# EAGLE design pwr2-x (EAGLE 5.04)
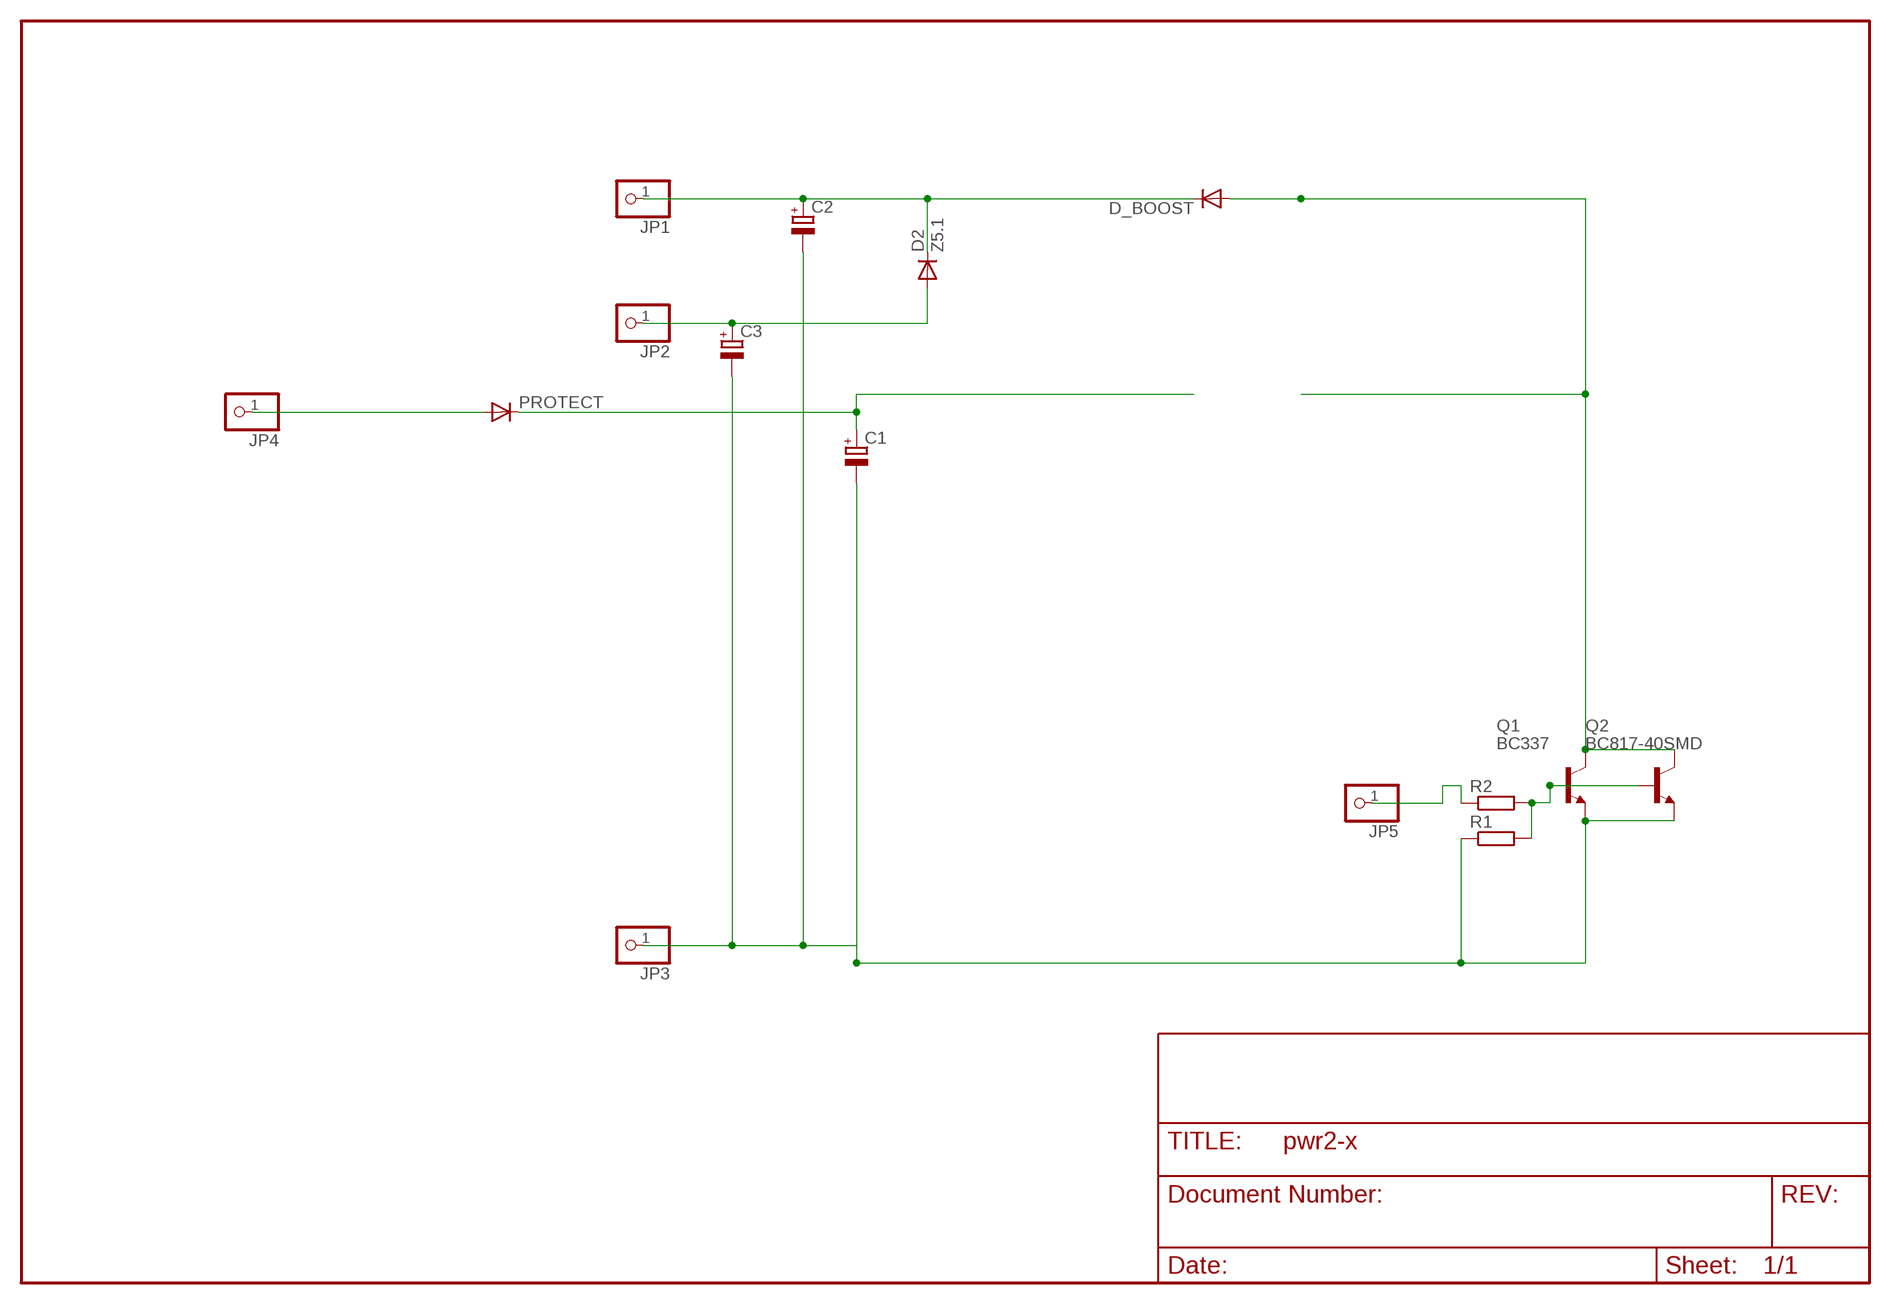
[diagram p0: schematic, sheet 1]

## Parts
C1  CPOL-EUE2.5-7  [E2,5-7]
C2  CPOL-EUE2.5-7  [E2,5-7]
C3  CPOL-EUE2-4  [E2-4]
D2  Z5.1  DIODE-D-7.5  [D-7.5]
D_BOOST  DIODE-D-10  [D-10]
JP1  PINHD-1X1  [1X01]
JP2  PINHD-1X1  [1X01]
JP3  PINHD-1X1  [1X01]
JP4  PINHD-1X1  [1X01]
JP5  PINHD-1X1  [1X01]
PROTECT  DIODE-D-5  [D-5]
Q1  BC337  [TO92]
Q2  BC817-40SMD  [SOT23-BEC]
R1  R-EU_0204/2V  [0204V]
R2  R-EU_0204/2V  [0204V]

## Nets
GND: C1.- C2.- C3.- JP3.1 Q1.1(E) Q2.E R1.1
HOTSPOT: D_BOOST.A Q1.3(C) Q2.C
N$1: Q1.2(B) Q2.B R1.2 R2.2
N$2: C1.+ PROTECT.C
N$3: JP5.1 R2.1
N$4: C3.+ D2.A JP2.1
N$6: JP4.1 PROTECT.A
N$7: C2.+ D2.C D_BOOST.C JP1.1

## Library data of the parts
C1-C3 = rcl(2):CPOL-EU: POLARIZED CAPACITOR, European symbol
D2 D_BOOST PROTECT = diode:DIODE-: DIODE
JP1-JP5 = pinhead:PINHD-1X1: PIN HEADER
Q1 = transistor-npn:BC337*: NPN Transistor
Q2 = transistor-npn:BC817*: NPN Transistor
R1 R2 = rcl-2:R-EU_: RESISTOR, European symbol

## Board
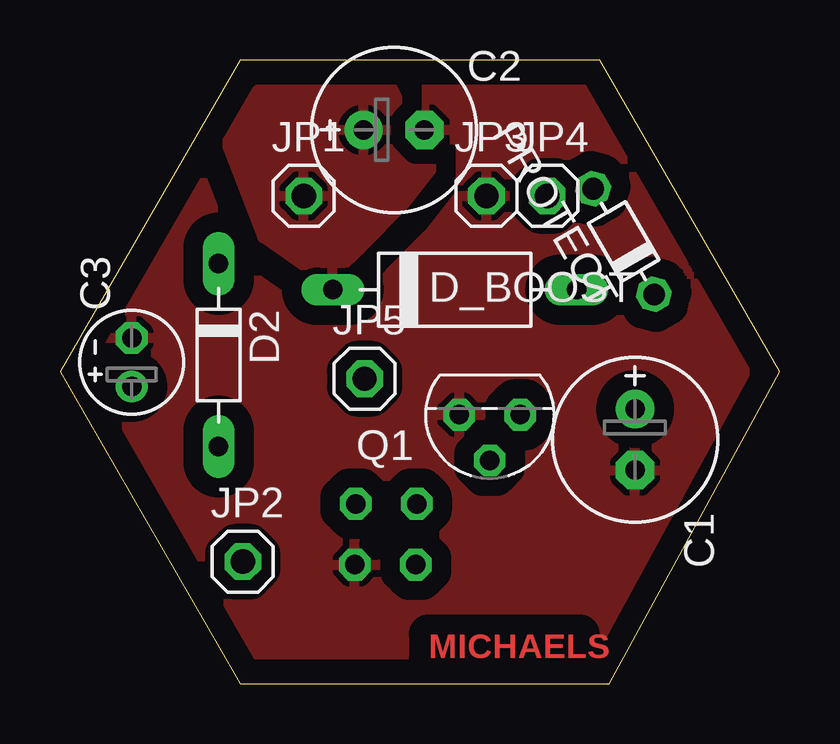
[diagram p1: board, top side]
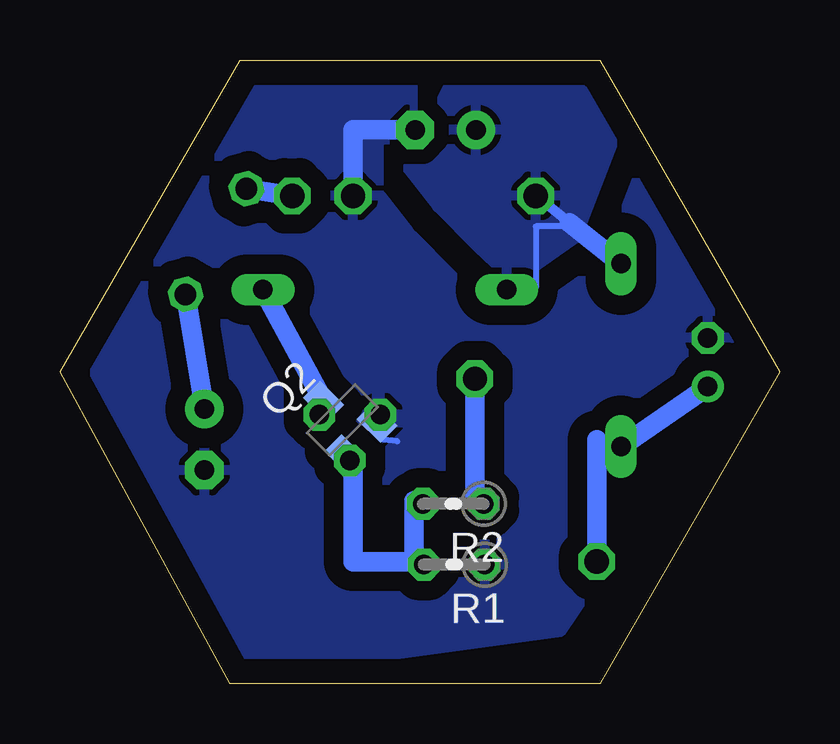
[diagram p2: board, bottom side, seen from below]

Size 30 x 25.98 mm. Coordinates in mm from the lower left corner, seen from the top.
Outline: 7.5,0 22.9,0 30,12.99 22.5,25.98 7.5,25.98 0,12.99 7.5,0
Copper layers (1*16): Top 0.035mm / dielectric 1.5mm / Bottom 0.035mm
Design rules "default": minimum track width 10mil, minimum drill 24mil, track to track 8mil, track to pad 8mil, pad to pad 8mil, via to via 8mil, smd to smd 8mil, copper to edge 40mil, drill to drill 8mil, minimum pad ring 10mil, minimum via ring 8mil, stop-mask expansion 4mil, vias tented up to drill 0mil, thermal gap 10mil

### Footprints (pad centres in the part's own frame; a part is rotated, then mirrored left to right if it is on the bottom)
E2,5-7 = drill 0.813 pad 1.6 round: + -1.27,0 | drill 0.813 pad 1.6 octagon: - 1.27,0
E2-4 = drill 0.813 pad 1.27 round: + -1.016,0 | drill 0.813 pad 1.27 octagon: - 1.016,0
D-7.5 = drill 0.813 long: A 3.81,0; C -3.81,0
D-10 = drill 0.813 long: A 5.08,0; C -5.08,0
1X01 = drill 1.016 octagon: 1 0,0
D-5 = drill 0.9 octagon: A 2.54,0; C -2.54,0
TO92 = drill 0.813 octagon: 1 1.27,0; 2 0,1.905; 3 -1.27,0
SOT23-BEC = smd 1 x 1.4: B -0.95,-1.1; C 0,1.1; E 0.95,-1.1
0204V = drill 0.813 octagon: 1 -1.27,0; 2 1.27,0

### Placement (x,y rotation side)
C1  23.98,10.16 270 top
C2  13.93,23.07 0 top
C3  2.99,13.39 90 top
D2  6.61,13.68 270 top
D_BOOST  16.45,16.41 0 top
JP1  10.16,20.32 0 top
JP2  7.62,5.08 0 top
JP3  17.78,20.32 0 top
JP4  20.32,20.32 0 top
JP5  12.7,12.7 0 top
PROTECT  23.5,18.41 120 top
Q1  17.92,11.2 180 top
Q2  18.23,10.98 45 bottom
R1  13.56,4.95 180 bottom
R2  13.6,7.49 180 bottom

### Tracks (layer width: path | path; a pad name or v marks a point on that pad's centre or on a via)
GND
  Bottom 0.254: Q2.E 16.51,10.16 15.93,10.09
  Bottom 0.813: C2.- 17.78,23.07 JP3.1
  pour Bottom (isolate 0.813, rank 3): -0.37,12.32 6.87,26.73 22.5,26.09 30.2,14.7 22.53,0.32 9.1,2.16 5.37,7.68
  pour Top (isolate 0.813, rank 3): 0.9,15.5 7.5,25.46 22.5,25.46 30.2,14.7 21.8,-0.38 6.64,0.7
HOTSPOT
  Bottom 0.406: Q2.C Q1.3
  Bottom 0.813: Q2.C D_BOOST.A
N$1
  Bottom 0.254: Q2.B 17.78,8.89 Q1.2 | 15.24,7.62 R2.2 | R1.2 15.24,5.08
  Bottom 0.813: 15.24,7.62 15.24,5.08 17.78,5.08 17.78,8.89
N$2
  Bottom 0.813: C1.+ PROTECT.C
N$3
  Bottom 0.254: R2.1 12.7,7.62
  Bottom 0.813: 12.7,7.62 JP5.1
N$4
  Bottom 0.254: 7.62,10.16 6.35,10.16 D2.A
  Bottom 0.813: D2.A C3.+ | JP2.1 7.62,10.16
N$6
  Bottom 0.813: PROTECT.A JP4.1
N$7
  Bottom 0.254: D_BOOST.C 10.16,16.51 10.16,19.05 8.89,19.05 8.76,19.21
  Bottom 0.406: 8.76,19.21 JP1.1
  Bottom 0.813: D2.C 8.76,19.21
  pour Top (isolate 0.61): 11.54,17.16 10.47,17.16 8.44,18.57 6.54,23.53 8.8,25.16 13.71,25.16 15.54,21.46 14.27,19.84 12.6,18.16
  pour Bottom (isolate 0.61): 11.54,17.16 10.47,17.16 8.44,18.57 6.54,23.53 8.8,25.16 13.71,25.16 15.54,21.46 14.27,19.84 12.6,18.16

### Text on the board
Top: MICHAELS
